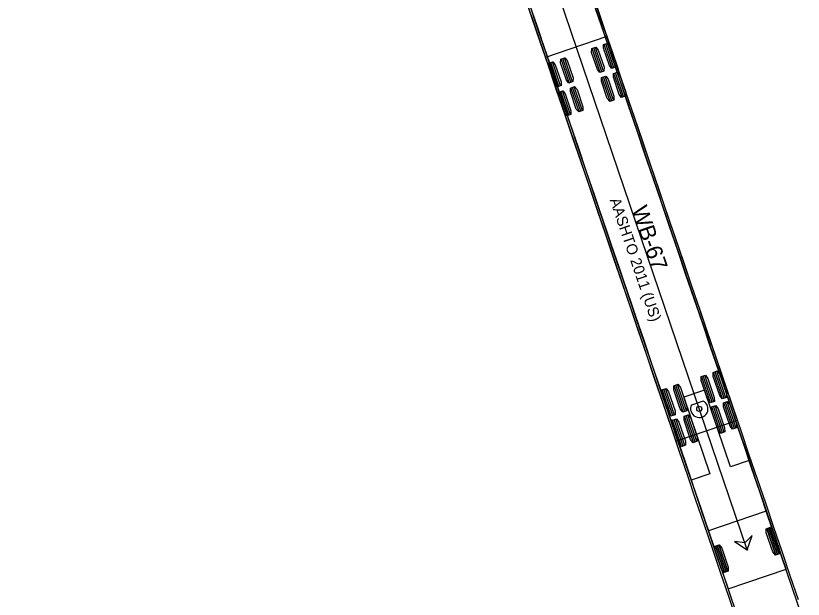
# Model space of a CAD drawing. Extents: x 916040 to 917457, y 328936 to 330267.
# Drawn here: x 916826.9 to 916930, y 328996.3 to 329072.6 of the extents above; entities that cross this region are included whole.
import ezdxf

# ---------------------------------------------------------------- set-up
doc = ezdxf.new("R2010")
doc.units = 0
for name, color, linetype in [('NB_LeftontoRoute25_WB67', 7, 'Continuous'), ('NB_RightontoRoute25_WB67', 7, 'Continuous'), ('NB_ThruontoManchester_WB67', 7, 'Continuous')]:
    doc.layers.add(name, color=color, linetype=linetype)

msp = doc.modelspace()

# ---------------------------------------------------------------- linework, layer by layer
at = {"layer": 'NB_LeftontoRoute25_WB67'}
for p, q in [((916922.62, 329002.7), (916826.94, 329284.22)), ((916904.27, 329069.86), (916896.23, 329067.13)), ((916921.34, 329019.69), (916904.27, 329069.86)), ((916903.61, 329065.26), (916902.55, 329068.38)), ((916903.83, 329065.33), (916902.77, 329068.45)), ((916904.96, 329065.71), (916903.9, 329068.84)), ((916905.18, 329065.79), (916904.11, 329068.91)), ((916905.39, 329065.86), (916904.33, 329068.98)), ((916903.4, 329065.18), (916902.33, 329068.31)), ((916896.23, 329067.13), (916913.29, 329016.95)), ((916897.78, 329063.27), (916896.72, 329066.4)), ((916898, 329063.34), (916896.93, 329066.47)), ((916898.21, 329063.42), (916897.15, 329066.54)), ((916899.34, 329063.8), (916898.28, 329066.93)), ((916899.56, 329063.88), (916898.5, 329067)), ((916899.78, 329063.95), (916898.71, 329067.07)), ((916904.68, 329061.39), (916903.62, 329064.52)), ((916904.9, 329061.47), (916903.84, 329064.59)), ((916905.12, 329061.54), (916904.06, 329064.67)), ((916906.25, 329061.93), (916905.18, 329065.05)), ((916906.46, 329062), (916905.4, 329065.12)), ((916906.68, 329062.07), (916905.62, 329065.2)), ((916901.06, 329060.16), (916900, 329063.29)), ((916899.07, 329059.48), (916898, 329062.61)), ((916899.28, 329059.56), (916898.22, 329062.68)), ((916899.5, 329059.63), (916898.44, 329062.76)), ((916900.63, 329060.02), (916899.57, 329063.14)), ((916900.85, 329060.09), (916899.78, 329063.21)), ((916917.84, 329021.95), (916916.66, 329025.42)), ((916918.05, 329022.02), (916916.87, 329025.49)), ((916918.27, 329022.09), (916917.09, 329025.56)), ((916919.4, 329022.48), (916918.22, 329025.95)), ((916919.62, 329022.55), (916918.44, 329026.02)), ((916919.83, 329022.62), (916918.65, 329026.1)), ((916914.26, 329020.73), (916913.08, 329024.2)), ((916914.47, 329020.8), (916913.29, 329024.27)), ((916914.69, 329020.88), (916913.51, 329024.35)), ((916912.69, 329020.2), (916911.51, 329023.67)), ((916912.91, 329020.27), (916911.73, 329023.74)), ((916913.13, 329020.34), (916911.95, 329023.82)), ((916917.03, 329023.61), (916914.32, 329022.68)), ((916920.44, 329013.57), (916917.03, 329023.61)), ((916914.32, 329022.68), (916917.73, 329012.65)), ((916916.85, 329022.18), (916915.32, 329021.66)), ((916920.97, 329018.57), (916919.79, 329022.05)), ((916921.19, 329018.65), (916920.01, 329022.12)), ((916919.19, 329017.97), (916918.01, 329021.44)), ((916919.41, 329018.04), (916918.23, 329021.51)), ((916919.62, 329018.12), (916918.44, 329021.59)), ((916920.75, 329018.5), (916919.57, 329021.97)), ((916915.61, 329016.75), (916914.43, 329020.22)), ((916915.82, 329016.82), (916914.64, 329020.3)), ((916916.04, 329016.9), (916914.86, 329020.37)), ((916914.04, 329016.22), (916912.86, 329019.69)), ((916914.26, 329016.29), (916913.08, 329019.77)), ((916913.29, 329016.95), (916921.34, 329019.69)), ((916914.48, 329016.37), (916913.3, 329019.84)), ((916921.34, 329019.69), (916921.34, 329019.69)), ((916922.87, 329014.4), (916920.44, 329013.57)), ((916927.7, 329000.19), (916922.87, 329014.4)), ((916917.73, 329012.65), (916915.3, 329011.82)), ((916915.3, 329011.82), (916920.12, 328997.62)), ((916926.57, 329002.1), (916925.39, 329005.57)), ((916926.78, 329002.17), (916925.6, 329005.64)), ((916926.35, 329002.03), (916925.17, 329005.5)), ((916919.64, 328999.75), (916918.46, 329003.22)), ((916919.86, 328999.82), (916918.68, 329003.29)), ((916920.08, 328999.89), (916918.9, 329003.36)), ((916920.12, 328997.62), (916927.7, 329000.19)), ((916927.7, 329000.19), (916927.7, 329000.19))]:
    msp.add_line(p, q, dxfattribs=at)
for points in [[(916902.39, 329075.39), (916903.47, 329072.23), (916904.54, 329069.07), (916905.61, 329065.92), (916905.72, 329065.6)], [(916894.06, 329074.31), (916895.13, 329071.16), (916896.2, 329068), (916897.28, 329064.85), (916898.35, 329061.69), (916899.42, 329058.53), (916900.49, 329055.38), (916901.57, 329052.22), (916902.64, 329049.07), (916903.71, 329045.91), (916904.78, 329042.75), (916905.86, 329039.6), (916906.93, 329036.44), (916908, 329033.28), (916909.08, 329030.13), (916910.15, 329026.97), (916911.22, 329023.82), (916912.29, 329020.66), (916913.37, 329017.5), (916914.44, 329014.35), (916915.51, 329011.19), (916916.58, 329008.04), (916917.66, 329004.88), (916918.73, 329001.72), (916918.84, 329001.41)], [(916902.71, 329073.73), (916903.78, 329070.58), (916904.85, 329067.42), (916905.92, 329064.26), (916907, 329061.11), (916908.07, 329057.95), (916909.14, 329054.8), (916910.21, 329051.64), (916911.29, 329048.48), (916912.36, 329045.33), (916913.43, 329042.17), (916914.5, 329039.02), (916915.58, 329035.86), (916916.65, 329032.7), (916917.72, 329029.55), (916918.8, 329026.39), (916919.87, 329023.23), (916920.94, 329020.08), (916922.01, 329016.92), (916923.09, 329013.77), (916924.16, 329010.61), (916925.23, 329007.45), (916926.3, 329004.3), (916926.41, 329003.98)], [(916894.35, 329072.65), (916895.42, 329069.49), (916896.49, 329066.34), (916897.57, 329063.18), (916897.67, 329062.87)]]:
    msp.add_lwpolyline(points, dxfattribs=at)
for points in [[(916903.88, 329065.35), (916903.34, 329065.16), (916903.03, 329065.55), (916902.27, 329067.79), (916902.28, 329068.29), (916902.82, 329068.47), (916903.13, 329068.09), (916903.9, 329065.84)], [(916905.45, 329065.88), (916904.9, 329065.69), (916904.59, 329066.08), (916903.83, 329068.33), (916903.84, 329068.82), (916904.38, 329069), (916904.7, 329068.62), (916905.46, 329066.37)], [(916898.27, 329063.44), (916897.73, 329063.25), (916897.41, 329063.63), (916896.65, 329065.88), (916896.66, 329066.38), (916897.2, 329066.56), (916897.52, 329066.18), (916898.28, 329063.93)], [(916899.83, 329063.97), (916899.29, 329063.78), (916898.98, 329064.17), (916898.21, 329066.42), (916898.22, 329066.91), (916898.77, 329067.09), (916899.08, 329066.71), (916899.84, 329064.46)], [(916905.17, 329061.56), (916904.63, 329061.38), (916904.32, 329061.76), (916903.55, 329064.01), (916903.57, 329064.5), (916904.11, 329064.68), (916904.42, 329064.3), (916905.19, 329062.05)], [(916906.73, 329062.09), (916906.19, 329061.91), (916905.88, 329062.29), (916905.12, 329064.54), (916905.13, 329065.03), (916905.67, 329065.22), (916905.98, 329064.83), (916906.75, 329062.58)], [(916901.12, 329060.18), (916900.58, 329060), (916900.26, 329060.38), (916899.5, 329062.63), (916899.51, 329063.12), (916900.05, 329063.31), (916900.37, 329062.92), (916901.13, 329060.67)], [(916899.55, 329059.65), (916899.01, 329059.47), (916898.7, 329059.85), (916897.94, 329062.1), (916897.95, 329062.59), (916898.49, 329062.77), (916898.8, 329062.39), (916899.57, 329060.14)], [(916918.33, 329022.11), (916917.78, 329021.93), (916917.46, 329022.36), (916916.61, 329024.86), (916916.6, 329025.4), (916917.15, 329025.58), (916917.47, 329025.15), (916918.32, 329022.65)], [(916919.89, 329022.64), (916919.35, 329022.46), (916919.02, 329022.89), (916918.17, 329025.39), (916918.17, 329025.93), (916918.71, 329026.11), (916919.04, 329025.68), (916919.89, 329023.18)], [(916914.74, 329020.89), (916914.2, 329020.71), (916913.87, 329021.14), (916913.02, 329023.64), (916913.02, 329024.18), (916913.56, 329024.37), (916913.89, 329023.93), (916914.74, 329021.44)], [(916913.18, 329020.36), (916912.64, 329020.18), (916912.31, 329020.61), (916911.46, 329023.11), (916911.46, 329023.65), (916912, 329023.83), (916912.33, 329023.4), (916913.18, 329020.9)], [(916921.24, 329018.67), (916920.7, 329018.48), (916920.37, 329018.91), (916919.52, 329021.41), (916919.52, 329021.95), (916920.06, 329022.14), (916920.39, 329021.71), (916921.24, 329019.21)], [(916919.68, 329018.13), (916919.14, 329017.95), (916918.81, 329018.38), (916917.96, 329020.88), (916917.96, 329021.42), (916918.5, 329021.61), (916918.83, 329021.18), (916919.67, 329018.68)], [(916916.09, 329016.92), (916915.55, 329016.73), (916915.22, 329017.16), (916914.38, 329019.66), (916914.37, 329020.2), (916914.91, 329020.39), (916915.24, 329019.96), (916916.09, 329017.46)], [(916914.53, 329016.39), (916913.99, 329016.2), (916913.66, 329016.63), (916912.81, 329019.13), (916912.81, 329019.67), (916913.35, 329019.86), (916913.68, 329019.43), (916914.53, 329016.93)], [(916926.84, 329002.19), (916926.3, 329002.01), (916925.97, 329002.44), (916925.12, 329004.94), (916925.12, 329005.48), (916925.66, 329005.66), (916925.99, 329005.23), (916926.84, 329002.73)], [(916922.62, 329002.7), (916923.27, 329004.59), (916922.3, 329003.64), (916920.96, 329003.81)], [(916920.13, 328999.91), (916919.59, 328999.73), (916919.26, 329000.16), (916918.41, 329002.66), (916918.41, 329003.2), (916918.95, 329003.38), (916919.28, 329002.95), (916920.13, 329000.45)]]:
    msp.add_lwpolyline(points, close=True, dxfattribs=at)
for centre, radius in [((916905.72, 329065.6), 0.0417), ((916897.67, 329062.87), 0.0417), ((916916.35, 329021.16), 0.34), ((916926.41, 329003.98), 0.0417), ((916922.62, 329002.7), 0.0417), ((916918.84, 329001.41), 0.0417)]:
    msp.add_circle(centre, radius, dxfattribs=at)
msp.add_arc((916916.35, 329021.16), 1.14, 153.7715, 63.7715, dxfattribs=at)
at = {"layer": 'NB_RightontoRoute25_WB67'}
for p, q in [((916922.62, 329002.7), (916826.94, 329284.22)), ((916925.12, 329007.77), (916917.55, 329005.2)), ((916929.95, 328993.57), (916925.12, 329007.77)), ((916925.39, 329005.57), (916926.57, 329002.1)), ((916925.6, 329005.64), (916926.78, 329002.17)), ((916917.55, 329005.2), (916922.38, 328990.99)), ((916917.55, 329005.2), (916917.55, 329005.2)), ((916925.17, 329005.5), (916926.35, 329002.03)), ((916918.46, 329003.22), (916919.64, 328999.75)), ((916918.68, 329003.29), (916919.86, 328999.82)), ((916918.9, 329003.36), (916920.08, 328999.89))]:
    msp.add_line(p, q, dxfattribs=at)
for points in [[(916921.28, 328993.44), (916920.21, 328996.6), (916919.14, 328999.75), (916918.06, 329002.91), (916916.99, 329006.06), (916915.92, 329009.22), (916914.85, 329012.38), (916913.77, 329015.53), (916912.7, 329018.69), (916911.63, 329021.84), (916910.55, 329025), (916909.48, 329028.16), (916908.41, 329031.31), (916907.34, 329034.47), (916906.26, 329037.63), (916905.19, 329040.78), (916904.12, 329043.94), (916903.05, 329047.09), (916901.97, 329050.25), (916900.9, 329053.41), (916899.83, 329056.56), (916898.75, 329059.72), (916897.68, 329062.87), (916896.61, 329066.03), (916895.54, 329069.19), (916894.46, 329072.34), (916893.39, 329075.5)], [(916929.33, 328996.17), (916928.26, 328999.33), (916927.18, 329002.49), (916926.11, 329005.64), (916925.04, 329008.8), (916923.97, 329011.96), (916922.89, 329015.11), (916921.82, 329018.27), (916920.75, 329021.42), (916919.67, 329024.58), (916918.6, 329027.74), (916917.53, 329030.89), (916916.46, 329034.05), (916915.38, 329037.2), (916914.31, 329040.36), (916913.24, 329043.52), (916912.17, 329046.67), (916911.09, 329049.83), (916910.02, 329052.99), (916908.95, 329056.14), (916907.88, 329059.3), (916906.8, 329062.45), (916905.73, 329065.61), (916904.66, 329068.77), (916903.58, 329071.92), (916902.51, 329075.08)], [(916918.84, 329001.41), (916917.76, 329004.56), (916916.69, 329007.72), (916915.62, 329010.88), (916914.55, 329014.03), (916913.47, 329017.19), (916912.4, 329020.34), (916911.33, 329023.5), (916910.26, 329026.66), (916909.18, 329029.81), (916908.11, 329032.97), (916907.04, 329036.13), (916905.96, 329039.28), (916904.89, 329042.44), (916903.82, 329045.59), (916902.75, 329048.75), (916901.67, 329051.91), (916900.6, 329055.06), (916899.53, 329058.22), (916898.46, 329061.37), (916897.38, 329064.53), (916896.31, 329067.69), (916895.24, 329070.84), (916894.17, 329074)], [(916926.41, 329003.98), (916925.34, 329007.14), (916924.27, 329010.29), (916923.19, 329013.45), (916922.12, 329016.61), (916921.05, 329019.76), (916919.98, 329022.92), (916918.9, 329026.08), (916917.83, 329029.23), (916916.76, 329032.39), (916915.68, 329035.54), (916914.61, 329038.7), (916913.54, 329041.86), (916912.47, 329045.01), (916911.39, 329048.17), (916910.32, 329051.32), (916909.25, 329054.48), (916908.18, 329057.64), (916907.1, 329060.79), (916906.03, 329063.95), (916904.96, 329067.11), (916903.89, 329070.26), (916902.81, 329073.42)]]:
    msp.add_lwpolyline(points, dxfattribs=at)
for points in [[(916925.12, 329005.48), (916925.66, 329005.66), (916925.99, 329005.23), (916926.84, 329002.73), (916926.84, 329002.19), (916926.3, 329002.01), (916925.97, 329002.44), (916925.12, 329004.94)], [(916918.41, 329003.2), (916918.95, 329003.38), (916919.28, 329002.95), (916920.13, 329000.45), (916920.13, 328999.91), (916919.59, 328999.73), (916919.26, 329000.16), (916918.41, 329002.66)]]:
    msp.add_lwpolyline(points, close=True, dxfattribs=at)
for centre in [(916926.41, 329003.98), (916922.62, 329002.7), (916918.84, 329001.41)]:
    msp.add_circle(centre, 0.0417, dxfattribs=at)
at = {"layer": 'NB_ThruontoManchester_WB67'}
for p, q in [((916922.62, 329002.7), (916826.94, 329284.22)), ((916904.27, 329069.86), (916896.23, 329067.13)), ((916921.34, 329019.69), (916904.27, 329069.86)), ((916903.61, 329065.26), (916902.55, 329068.38)), ((916903.83, 329065.33), (916902.77, 329068.45)), ((916904.96, 329065.71), (916903.9, 329068.84)), ((916905.18, 329065.79), (916904.11, 329068.91)), ((916905.39, 329065.86), (916904.33, 329068.98)), ((916903.4, 329065.18), (916902.33, 329068.31)), ((916896.23, 329067.13), (916913.29, 329016.95)), ((916897.78, 329063.27), (916896.72, 329066.4)), ((916898, 329063.34), (916896.93, 329066.47)), ((916898.21, 329063.42), (916897.15, 329066.54)), ((916899.34, 329063.8), (916898.28, 329066.93)), ((916899.56, 329063.88), (916898.5, 329067)), ((916899.78, 329063.95), (916898.71, 329067.07)), ((916904.68, 329061.39), (916903.62, 329064.52)), ((916904.9, 329061.47), (916903.84, 329064.59)), ((916905.12, 329061.54), (916904.06, 329064.67)), ((916906.25, 329061.93), (916905.18, 329065.05)), ((916906.46, 329062), (916905.4, 329065.12)), ((916906.68, 329062.07), (916905.62, 329065.2)), ((916901.06, 329060.16), (916900, 329063.29)), ((916899.07, 329059.48), (916898, 329062.61)), ((916899.28, 329059.56), (916898.22, 329062.68)), ((916899.5, 329059.63), (916898.44, 329062.76)), ((916900.63, 329060.02), (916899.57, 329063.14)), ((916900.85, 329060.09), (916899.78, 329063.21)), ((916917.84, 329021.95), (916916.66, 329025.42)), ((916918.05, 329022.02), (916916.87, 329025.49)), ((916918.27, 329022.09), (916917.09, 329025.56)), ((916919.4, 329022.48), (916918.22, 329025.95)), ((916919.62, 329022.55), (916918.44, 329026.02)), ((916919.83, 329022.62), (916918.65, 329026.1)), ((916914.26, 329020.73), (916913.08, 329024.2)), ((916914.47, 329020.8), (916913.29, 329024.27)), ((916914.69, 329020.88), (916913.51, 329024.35)), ((916912.69, 329020.2), (916911.51, 329023.67)), ((916912.91, 329020.27), (916911.73, 329023.74)), ((916913.13, 329020.34), (916911.95, 329023.82)), ((916917.03, 329023.61), (916914.32, 329022.68)), ((916920.44, 329013.57), (916917.03, 329023.61)), ((916914.32, 329022.68), (916917.73, 329012.65)), ((916916.85, 329022.18), (916915.32, 329021.66)), ((916920.97, 329018.57), (916919.79, 329022.05)), ((916921.19, 329018.65), (916920.01, 329022.12)), ((916919.19, 329017.97), (916918.01, 329021.44)), ((916919.41, 329018.04), (916918.23, 329021.51)), ((916919.62, 329018.12), (916918.44, 329021.59)), ((916920.75, 329018.5), (916919.57, 329021.97)), ((916915.61, 329016.75), (916914.43, 329020.22)), ((916915.82, 329016.82), (916914.64, 329020.3)), ((916916.04, 329016.9), (916914.86, 329020.37)), ((916914.04, 329016.22), (916912.86, 329019.69)), ((916914.26, 329016.29), (916913.08, 329019.77)), ((916913.29, 329016.95), (916921.34, 329019.69)), ((916914.48, 329016.37), (916913.3, 329019.84)), ((916921.34, 329019.69), (916921.34, 329019.69)), ((916922.87, 329014.4), (916920.44, 329013.57)), ((916927.7, 329000.19), (916922.87, 329014.4)), ((916917.73, 329012.65), (916915.3, 329011.82)), ((916915.3, 329011.82), (916920.12, 328997.62)), ((916925.12, 329007.77), (916917.55, 329005.2)), ((916925.12, 329007.77), (916917.55, 329005.2)), ((916929.95, 328993.57), (916925.12, 329007.77)), ((916929.95, 328993.57), (916925.12, 329007.77)), ((916925.39, 329005.57), (916926.57, 329002.1)), ((916925.39, 329005.57), (916926.57, 329002.1)), ((916926.57, 329002.1), (916925.39, 329005.57)), ((916925.6, 329005.64), (916926.78, 329002.17)), ((916925.6, 329005.64), (916926.78, 329002.17)), ((916926.78, 329002.17), (916925.6, 329005.64)), ((916917.55, 329005.2), (916922.38, 328990.99)), ((916917.55, 329005.2), (916917.55, 329005.2)), ((916917.55, 329005.2), (916922.38, 328990.99)), ((916917.55, 329005.2), (916917.55, 329005.2)), ((916925.17, 329005.5), (916926.35, 329002.03)), ((916925.17, 329005.5), (916926.35, 329002.03)), ((916926.35, 329002.03), (916925.17, 329005.5)), ((916918.46, 329003.22), (916919.64, 328999.75)), ((916918.46, 329003.22), (916919.64, 328999.75)), ((916919.64, 328999.75), (916918.46, 329003.22)), ((916918.68, 329003.29), (916919.86, 328999.82)), ((916918.68, 329003.29), (916919.86, 328999.82)), ((916919.86, 328999.82), (916918.68, 329003.29)), ((916918.9, 329003.36), (916920.08, 328999.89)), ((916918.9, 329003.36), (916920.08, 328999.89)), ((916920.08, 328999.89), (916918.9, 329003.36)), ((916920.12, 328997.62), (916927.7, 329000.19)), ((916927.7, 329000.19), (916927.7, 329000.19))]:
    msp.add_line(p, q, dxfattribs=at)
for points in [[(916902.17, 329075.31), (916903.24, 329072.16), (916904.31, 329069), (916905.39, 329065.84), (916906.46, 329062.69), (916907.53, 329059.53), (916908.6, 329056.37), (916909.68, 329053.22), (916910.75, 329050.06), (916911.82, 329046.91), (916912.9, 329043.75), (916913.97, 329040.59), (916915.04, 329037.44), (916916.11, 329034.28), (916917.19, 329031.13), (916918.26, 329027.97), (916919.33, 329024.81), (916920.4, 329021.66), (916921.48, 329018.5), (916922.55, 329015.34), (916923.62, 329012.19), (916924.7, 329009.03), (916925.77, 329005.88), (916926.41, 329003.98)], [(916893.81, 329074.23), (916894.88, 329071.07), (916895.96, 329067.92), (916897.03, 329064.76), (916897.67, 329062.87)], [(916902.93, 329073.81), (916904, 329070.65), (916905.08, 329067.5), (916905.72, 329065.6)], [(916894.59, 329072.74), (916895.67, 329069.58), (916896.74, 329066.42), (916897.81, 329063.27), (916898.89, 329060.11), (916899.96, 329056.96), (916901.03, 329053.8), (916902.1, 329050.64), (916903.18, 329047.49), (916904.25, 329044.33), (916905.32, 329041.18), (916906.39, 329038.02), (916907.47, 329034.86), (916908.54, 329031.71), (916909.61, 329028.55), (916910.68, 329025.39), (916911.76, 329022.24), (916912.83, 329019.08), (916913.9, 329015.93), (916914.98, 329012.77), (916916.05, 329009.61), (916917.12, 329006.46), (916918.19, 329003.3), (916918.84, 329001.41)]]:
    msp.add_lwpolyline(points, dxfattribs=at)
for points in [[(916903.88, 329065.35), (916903.34, 329065.16), (916903.03, 329065.55), (916902.27, 329067.79), (916902.28, 329068.29), (916902.82, 329068.47), (916903.13, 329068.09), (916903.9, 329065.84)], [(916905.45, 329065.88), (916904.9, 329065.69), (916904.59, 329066.08), (916903.83, 329068.33), (916903.84, 329068.82), (916904.38, 329069), (916904.7, 329068.62), (916905.46, 329066.37)], [(916898.27, 329063.44), (916897.73, 329063.25), (916897.41, 329063.63), (916896.65, 329065.88), (916896.66, 329066.38), (916897.2, 329066.56), (916897.52, 329066.18), (916898.28, 329063.93)], [(916899.83, 329063.97), (916899.29, 329063.78), (916898.98, 329064.17), (916898.21, 329066.42), (916898.22, 329066.91), (916898.77, 329067.09), (916899.08, 329066.71), (916899.84, 329064.46)], [(916905.17, 329061.56), (916904.63, 329061.38), (916904.32, 329061.76), (916903.55, 329064.01), (916903.57, 329064.5), (916904.11, 329064.68), (916904.42, 329064.3), (916905.19, 329062.05)], [(916906.73, 329062.09), (916906.19, 329061.91), (916905.88, 329062.29), (916905.12, 329064.54), (916905.13, 329065.03), (916905.67, 329065.22), (916905.98, 329064.83), (916906.75, 329062.58)], [(916901.12, 329060.18), (916900.58, 329060), (916900.26, 329060.38), (916899.5, 329062.63), (916899.51, 329063.12), (916900.05, 329063.31), (916900.37, 329062.92), (916901.13, 329060.67)], [(916899.55, 329059.65), (916899.01, 329059.47), (916898.7, 329059.85), (916897.94, 329062.1), (916897.95, 329062.59), (916898.49, 329062.77), (916898.8, 329062.39), (916899.57, 329060.14)], [(916918.33, 329022.11), (916917.78, 329021.93), (916917.46, 329022.36), (916916.61, 329024.86), (916916.6, 329025.4), (916917.15, 329025.58), (916917.47, 329025.15), (916918.32, 329022.65)], [(916919.89, 329022.64), (916919.35, 329022.46), (916919.02, 329022.89), (916918.17, 329025.39), (916918.17, 329025.93), (916918.71, 329026.11), (916919.04, 329025.68), (916919.89, 329023.18)], [(916914.74, 329020.89), (916914.2, 329020.71), (916913.87, 329021.14), (916913.02, 329023.64), (916913.02, 329024.18), (916913.56, 329024.37), (916913.89, 329023.93), (916914.74, 329021.44)], [(916913.18, 329020.36), (916912.64, 329020.18), (916912.31, 329020.61), (916911.46, 329023.11), (916911.46, 329023.65), (916912, 329023.83), (916912.33, 329023.4), (916913.18, 329020.9)], [(916921.24, 329018.67), (916920.7, 329018.48), (916920.37, 329018.91), (916919.52, 329021.41), (916919.52, 329021.95), (916920.06, 329022.14), (916920.39, 329021.71), (916921.24, 329019.21)], [(916919.68, 329018.13), (916919.14, 329017.95), (916918.81, 329018.38), (916917.96, 329020.88), (916917.96, 329021.42), (916918.5, 329021.61), (916918.83, 329021.18), (916919.67, 329018.68)], [(916916.09, 329016.92), (916915.55, 329016.73), (916915.22, 329017.16), (916914.38, 329019.66), (916914.37, 329020.2), (916914.91, 329020.39), (916915.24, 329019.96), (916916.09, 329017.46)], [(916914.53, 329016.39), (916913.99, 329016.2), (916913.66, 329016.63), (916912.81, 329019.13), (916912.81, 329019.67), (916913.35, 329019.86), (916913.68, 329019.43), (916914.53, 329016.93)], [(916925.12, 329005.48), (916925.66, 329005.66), (916925.99, 329005.23), (916926.84, 329002.73), (916926.84, 329002.19), (916926.3, 329002.01), (916925.97, 329002.44), (916925.12, 329004.94)], [(916925.12, 329005.48), (916925.66, 329005.66), (916925.99, 329005.23), (916926.84, 329002.73), (916926.84, 329002.19), (916926.3, 329002.01), (916925.97, 329002.44), (916925.12, 329004.94)], [(916926.84, 329002.19), (916926.3, 329002.01), (916925.97, 329002.44), (916925.12, 329004.94), (916925.12, 329005.48), (916925.66, 329005.66), (916925.99, 329005.23), (916926.84, 329002.73)], [(916922.62, 329002.7), (916923.27, 329004.59), (916922.3, 329003.64), (916920.96, 329003.81)], [(916918.41, 329003.2), (916918.95, 329003.38), (916919.28, 329002.95), (916920.13, 329000.45), (916920.13, 328999.91), (916919.59, 328999.73), (916919.26, 329000.16), (916918.41, 329002.66)], [(916918.41, 329003.2), (916918.95, 329003.38), (916919.28, 329002.95), (916920.13, 329000.45), (916920.13, 328999.91), (916919.59, 328999.73), (916919.26, 329000.16), (916918.41, 329002.66)], [(916920.13, 328999.91), (916919.59, 328999.73), (916919.26, 329000.16), (916918.41, 329002.66), (916918.41, 329003.2), (916918.95, 329003.38), (916919.28, 329002.95), (916920.13, 329000.45)]]:
    msp.add_lwpolyline(points, close=True, dxfattribs=at)
for centre, radius in [((916905.72, 329065.6), 0.0417), ((916897.67, 329062.87), 0.0417), ((916916.35, 329021.16), 0.34), ((916926.41, 329003.98), 0.0417), ((916922.62, 329002.7), 0.0417), ((916918.84, 329001.41), 0.0417)]:
    msp.add_circle(centre, radius, dxfattribs=at)
msp.add_arc((916916.35, 329021.16), 1.14, 153.7715, 63.7715, dxfattribs=at)

# ---------------------------------------------------------------- texts
at = {"layer": 'NB_LeftontoRoute25_WB67'}
for s, height, p in [('AASHTO 2011 (US)', 1.4167, (916904.62, 329048.49)), ('WB-67', 2.125, (916907.46, 329047.29))]:
    msp.add_text(s, height=height, rotation=288.7838, dxfattribs=at).set_placement(p)
at = {"layer": 'NB_ThruontoManchester_WB67'}
for s, height, p in [('AASHTO 2011 (US)', 1.4167, (916904.62, 329048.49)), ('WB-67', 2.125, (916907.46, 329047.29))]:
    msp.add_text(s, height=height, rotation=288.7837, dxfattribs=at).set_placement(p)

doc.saveas('drawing.dxf')
